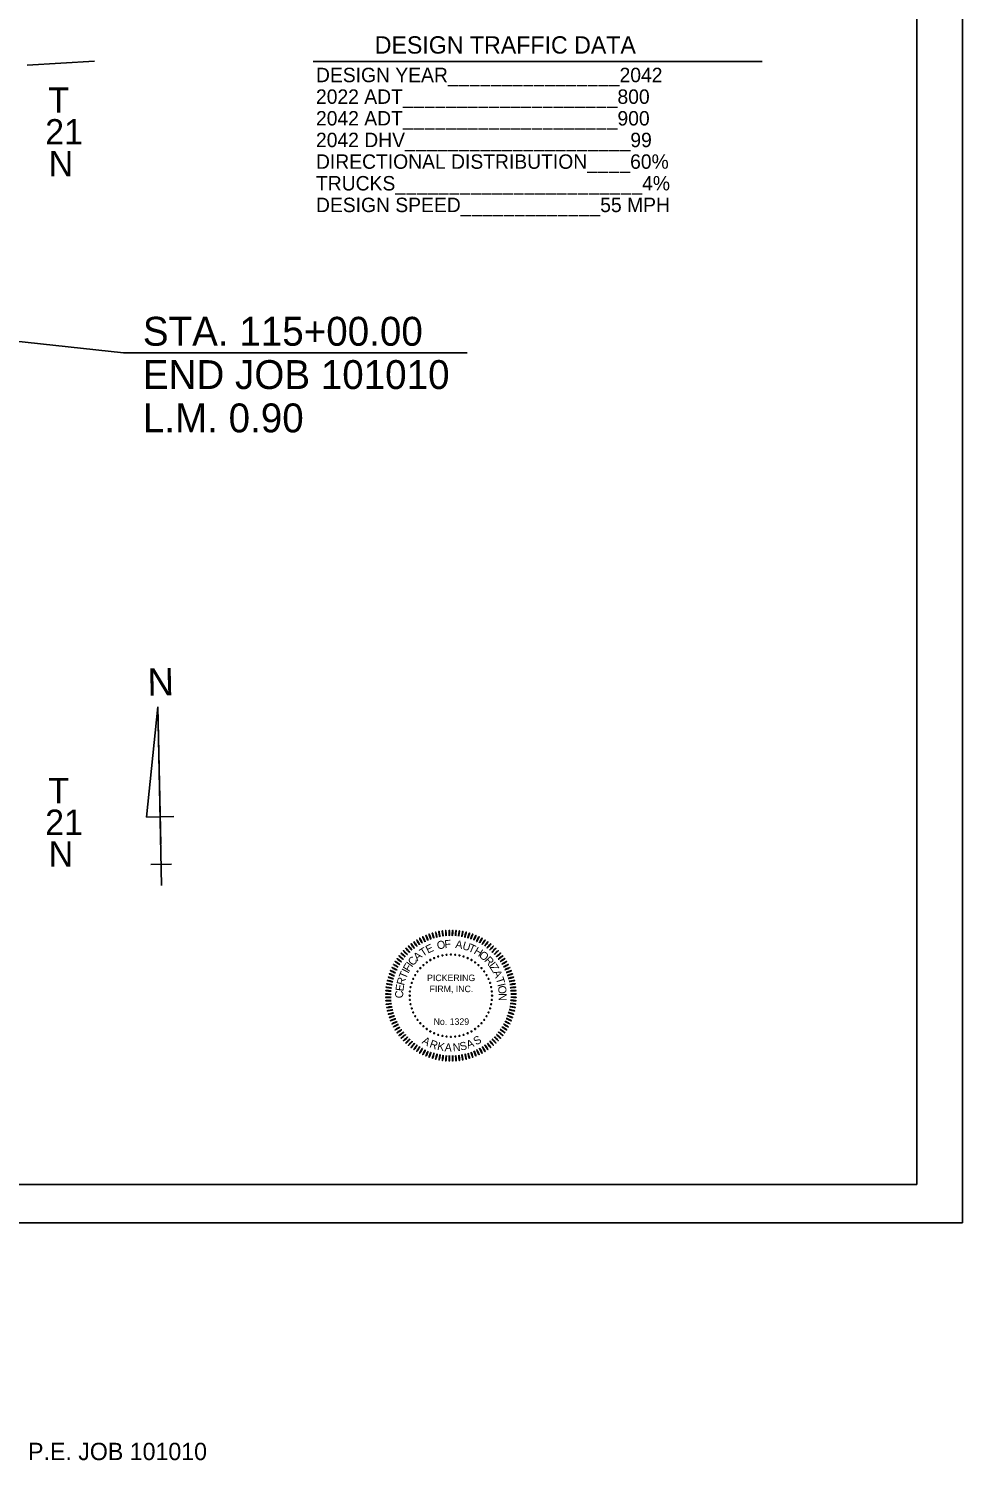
# Model space of a CAD drawing. Extents: x 1369885 to 1370219, y 379980 to 380218.
# Drawn here: x 1370121.7 to 1370218.7, y 379979.9 to 380128.7 of the extents above; entities that cross this region are included whole.
import ezdxf

# ---------------------------------------------------------------- set-up
doc = ezdxf.new("R2010")
doc.units = 0
for name, color, linetype in [('Default', 7, 'Continuous'), ('G-COA-ANNO', 7, 'Continuous'), ('G-COA-LINE', 7, 'Continuous'), ('Level 1', 7, 'Continuous'), ('Level 30', 7, 'Continuous'), ('Page Text', 7, 'Continuous'), ('R_Draft', 7, 'Continuous'), ('R_No Plot', 7, 'Continuous'), ('STAMP_PE_FOSTER-SIGNATURE', 7, 'Continuous'), ('V-ANNO', 7, 'Continuous')]:
    doc.layers.add(name, color=color, linetype=linetype)

# ---------------------------------------------------------------- blocks, each defined once
blk = doc.blocks.new('Pickering-COA AR-ENG')
at = {"layer": 'G-COA-LINE'}
for centre in [(-1.311, 4.686), (-1.311, 4.686), (-1.155, 4.812), (-1.155, 4.812), (-0.987, 4.922), (-0.987, 4.922), (-0.808, 5.013), (-0.808, 5.013), (-0.62, 5.085), (-0.62, 5.085), (-0.427, 5.137), (-0.427, 5.137), (-0.228, 5.168), (-0.228, 5.168), (-0.028, 5.179), (-0.028, 5.179), (0.173, 5.168), (0.173, 5.168), (0.371, 5.137), (0.371, 5.137), (0.565, 5.085), (0.565, 5.085), (0.752, 5.013), (0.752, 5.013), (0.931, 4.922), (0.931, 4.922), (1.099, 4.812), (1.099, 4.812), (1.255, 4.686), (1.255, 4.686), (-1.78, 4.041), (-1.78, 4.041), (-1.689, 4.22), (-1.689, 4.22), (-1.579, 4.388), (-1.579, 4.388), (-1.453, 4.544), (-1.453, 4.544), (1.397, 4.544), (1.397, 4.544), (1.524, 4.388), (1.524, 4.388), (1.633, 4.22), (1.633, 4.22), (1.724, 4.041), (1.724, 4.041), (-1.935, 3.461), (-1.935, 3.461), (-1.904, 3.66), (-1.904, 3.66), (-1.852, 3.854), (-1.852, 3.854), (1.796, 3.854), (1.796, 3.854), (1.848, 3.66), (1.848, 3.66), (1.879, 3.461), (1.879, 3.461), (-1.946, 3.261), (-1.946, 3.261), (-1.935, 3.061), (-1.935, 3.061), (-1.904, 2.862), (-1.904, 2.862), (-1.852, 2.668), (-1.852, 2.668), (1.796, 2.668), (1.796, 2.668), (1.848, 2.862), (1.848, 2.862), (1.879, 3.061), (1.879, 3.061), (1.89, 3.261), (1.89, 3.261), (-1.78, 2.481), (-1.78, 2.481), (-1.689, 2.302), (-1.689, 2.302), (-1.579, 2.134), (-1.579, 2.134), (-1.453, 1.978), (-1.453, 1.978), (1.397, 1.978), (1.397, 1.978), (1.524, 2.134), (1.524, 2.134), (1.633, 2.302), (1.633, 2.302), (1.724, 2.481), (1.724, 2.481), (-1.311, 1.836), (-1.311, 1.836), (-1.155, 1.709), (-1.155, 1.709), (-0.987, 1.6), (-0.987, 1.6), (-0.808, 1.509), (-0.808, 1.509), (-0.62, 1.437), (-0.62, 1.437), (-0.427, 1.385), (-0.427, 1.385), (-0.228, 1.354), (-0.228, 1.354), (-0.028, 1.343), (-0.028, 1.343), (0.173, 1.354), (0.173, 1.354), (0.371, 1.385), (0.371, 1.385), (0.565, 1.437), (0.565, 1.437), (0.752, 1.509), (0.752, 1.509), (0.931, 1.6), (0.931, 1.6), (1.099, 1.709), (1.099, 1.709), (1.255, 1.836), (1.255, 1.836)]:
    blk.add_circle(centre, 0.0229, dxfattribs=at)
for centre, major_axis in [((-1.287, 5.894), (0.053, -0.119)), ((-1.287, 5.894), (0.053, -0.119)), ((-1.147, 5.956), (0.047, -0.121)), ((-1.147, 5.956), (0.047, -0.121)), ((-1.005, 6.011), (0.04, -0.124)), ((-1.005, 6.011), (0.04, -0.124)), ((-0.86, 6.058), (0.034, -0.126)), ((-0.86, 6.058), (0.034, -0.126)), ((-0.712, 6.098), (0.027, -0.127)), ((-0.712, 6.098), (0.027, -0.127)), ((-0.563, 6.13), (0.02, -0.128)), ((-0.563, 6.13), (0.02, -0.128)), ((-0.412, 6.154), (0.014, -0.129)), ((-0.412, 6.154), (0.014, -0.129)), ((-0.26, 6.17), (0.006, -0.13)), ((-0.26, 6.17), (0.006, -0.13)), ((-0.107, 6.178), (0, -0.13)), ((-0.107, 6.178), (0, -0.13)), ((0.045, 6.178), (-0.007, -0.13)), ((0.045, 6.178), (-0.007, -0.13)), ((0.198, 6.171), (-0.014, -0.129)), ((0.198, 6.171), (-0.014, -0.129)), ((0.35, 6.155), (-0.02, -0.128)), ((0.35, 6.155), (-0.02, -0.128)), ((0.501, 6.131), (-0.027, -0.127)), ((0.501, 6.131), (-0.027, -0.127)), ((0.65, 6.099), (-0.034, -0.126)), ((0.65, 6.099), (-0.034, -0.126)), ((0.798, 6.06), (-0.04, -0.124)), ((0.798, 6.06), (-0.04, -0.124)), ((0.943, 6.013), (-0.047, -0.121)), ((0.943, 6.013), (-0.047, -0.121)), ((1.086, 5.958), (-0.053, -0.119)), ((1.086, 5.958), (-0.053, -0.119)), ((1.225, 5.896), (-0.059, -0.116)), ((1.225, 5.896), (-0.059, -0.116)), ((-2.147, 5.268), (0.092, -0.092)), ((-2.147, 5.268), (0.092, -0.092)), ((-2.039, 5.376), (0.087, -0.0967)), ((-2.039, 5.376), (0.087, -0.0967)), ((-1.925, 5.478), (0.082, -0.101)), ((-1.925, 5.478), (0.082, -0.101)), ((-1.807, 5.574), (0.076, -0.105)), ((-1.807, 5.574), (0.076, -0.105)), ((-1.683, 5.664), (0.071, -0.109)), ((-1.683, 5.664), (0.071, -0.109)), ((-1.555, 5.748), (0.065, -0.113)), ((-1.555, 5.748), (0.065, -0.113)), ((-1.423, 5.824), (0.059, -0.116)), ((-1.423, 5.824), (0.059, -0.116)), ((1.362, 5.827), (-0.065, -0.113)), ((1.362, 5.827), (-0.065, -0.113)), ((1.494, 5.751), (-0.071, -0.109)), ((1.494, 5.751), (-0.071, -0.109)), ((1.622, 5.668), (-0.076, -0.105)), ((1.622, 5.668), (-0.076, -0.105)), ((1.746, 5.578), (-0.082, -0.101)), ((1.746, 5.578), (-0.082, -0.101)), ((1.865, 5.482), (-0.087, -0.0967)), ((1.865, 5.482), (-0.087, -0.0967)), ((1.978, 5.38), (-0.092, -0.092)), ((1.978, 5.38), (-0.092, -0.092)), ((2.087, 5.272), (-0.0967, -0.087)), ((2.087, 5.272), (-0.0967, -0.087)), ((-2.594, 4.651), (0.113, -0.065)), ((-2.594, 4.651), (0.113, -0.065)), ((-2.517, 4.783), (0.109, -0.071)), ((-2.517, 4.783), (0.109, -0.071)), ((-2.434, 4.911), (0.105, -0.076)), ((-2.434, 4.911), (0.105, -0.076)), ((-2.345, 5.035), (0.101, -0.082)), ((-2.345, 5.035), (0.101, -0.082)), ((-2.249, 5.154), (0.0967, -0.087)), ((-2.249, 5.154), (0.0967, -0.087)), ((2.189, 5.159), (-0.101, -0.082)), ((2.189, 5.159), (-0.101, -0.082)), ((2.285, 5.04), (-0.105, -0.076)), ((2.285, 5.04), (-0.105, -0.076)), ((2.375, 4.917), (-0.109, -0.071)), ((2.375, 4.917), (-0.109, -0.071)), ((2.458, 4.789), (-0.113, -0.065)), ((2.458, 4.789), (-0.113, -0.065)), ((2.535, 4.657), (-0.116, -0.059)), ((2.535, 4.657), (-0.116, -0.059)), ((-2.827, 4.087), (0.124, -0.04)), ((-2.827, 4.087), (0.124, -0.04)), ((-2.779, 4.232), (0.121, -0.047)), ((-2.779, 4.232), (0.121, -0.047)), ((-2.725, 4.375), (0.119, -0.053)), ((-2.725, 4.375), (0.119, -0.053)), ((-2.663, 4.515), (0.116, -0.059)), ((-2.663, 4.515), (0.116, -0.059)), ((2.604, 4.521), (-0.119, -0.053)), ((2.604, 4.521), (-0.119, -0.053)), ((2.667, 4.381), (-0.121, -0.047)), ((2.667, 4.381), (-0.121, -0.047)), ((2.722, 4.238), (-0.124, -0.04)), ((2.722, 4.238), (-0.124, -0.04)), ((2.769, 4.093), (-0.126, -0.034)), ((2.769, 4.093), (-0.126, -0.034)), ((-2.945, 3.334), (0.13, -0.007)), ((-2.945, 3.334), (0.13, -0.007)), ((-2.937, 3.487), (0.129, -0.014)), ((-2.937, 3.487), (0.129, -0.014)), ((-2.921, 3.639), (0.128, -0.02)), ((-2.921, 3.639), (0.128, -0.02)), ((-2.897, 3.79), (0.127, -0.027)), ((-2.897, 3.79), (0.127, -0.027)), ((-2.866, 3.939), (0.126, -0.034)), ((-2.866, 3.939), (0.126, -0.034)), ((2.809, 3.946), (-0.127, -0.027)), ((2.809, 3.946), (-0.127, -0.027)), ((2.841, 3.796), (-0.128, -0.02)), ((2.841, 3.796), (-0.128, -0.02)), ((2.865, 3.646), (-0.129, -0.013)), ((2.865, 3.646), (-0.129, -0.013)), ((2.881, 3.494), (-0.13, -0.007)), ((2.881, 3.494), (-0.13, -0.007)), ((2.889, 3.341), (-0.13, 0)), ((2.889, 3.341), (-0.13, 0)), ((-2.945, 3.182), (0.13, 0)), ((-2.945, 3.182), (0.13, 0)), ((-2.936, 3.029), (0.13, 0.007)), ((-2.936, 3.029), (0.13, 0.007)), ((-2.92, 2.876), (0.129, 0.013)), ((-2.92, 2.876), (0.129, 0.013)), ((-2.896, 2.726), (0.128, 0.02)), ((-2.896, 2.726), (0.128, 0.02)), ((2.842, 2.733), (-0.127, 0.027)), ((2.842, 2.733), (-0.127, 0.027)), ((2.866, 2.884), (-0.128, 0.02)), ((2.866, 2.884), (-0.128, 0.02)), ((2.881, 3.036), (-0.129, 0.014)), ((2.881, 3.036), (-0.129, 0.014)), ((2.889, 3.188), (-0.13, 0.006)), ((2.889, 3.188), (-0.13, 0.006)), ((-2.864, 2.577), (0.127, 0.027)), ((-2.864, 2.577), (0.127, 0.027)), ((-2.825, 2.429), (0.126, 0.034)), ((-2.825, 2.429), (0.126, 0.034)), ((-2.777, 2.284), (0.124, 0.04)), ((-2.777, 2.284), (0.124, 0.04)), ((-2.722, 2.142), (0.121, 0.047)), ((-2.722, 2.142), (0.121, 0.047)), ((-2.66, 2.002), (0.119, 0.053)), ((-2.66, 2.002), (0.119, 0.053)), ((2.607, 2.008), (-0.116, 0.059)), ((2.607, 2.008), (-0.116, 0.059)), ((2.669, 2.148), (-0.119, 0.053)), ((2.669, 2.148), (-0.119, 0.053)), ((2.724, 2.29), (-0.121, 0.047)), ((2.724, 2.29), (-0.121, 0.047)), ((2.771, 2.436), (-0.124, 0.04)), ((2.771, 2.436), (-0.124, 0.04)), ((2.81, 2.583), (-0.126, 0.034)), ((2.81, 2.583), (-0.126, 0.034)), ((-2.591, 1.866), (0.116, 0.059)), ((-2.591, 1.866), (0.116, 0.059)), ((-2.514, 1.734), (0.113, 0.065)), ((-2.514, 1.734), (0.113, 0.065)), ((-2.431, 1.606), (0.109, 0.071)), ((-2.431, 1.606), (0.109, 0.071)), ((-2.341, 1.482), (0.105, 0.076)), ((-2.341, 1.482), (0.105, 0.076)), ((-2.244, 1.364), (0.101, 0.082)), ((-2.244, 1.364), (0.101, 0.082)), ((-2.142, 1.25), (0.0967, 0.087)), ((-2.142, 1.25), (0.0967, 0.087)), ((2.091, 1.255), (-0.092, 0.092)), ((2.091, 1.255), (-0.092, 0.092)), ((2.193, 1.369), (-0.0967, 0.087)), ((2.193, 1.369), (-0.0967, 0.087)), ((2.289, 1.488), (-0.101, 0.082)), ((2.289, 1.488), (-0.101, 0.082)), ((2.379, 1.611), (-0.105, 0.076)), ((2.379, 1.611), (-0.105, 0.076)), ((2.462, 1.739), (-0.109, 0.071)), ((2.462, 1.739), (-0.109, 0.071)), ((2.538, 1.872), (-0.113, 0.065)), ((2.538, 1.872), (-0.113, 0.065)), ((-2.034, 1.142), (0.092, 0.092)), ((-2.034, 1.142), (0.092, 0.092)), ((-1.92, 1.04), (0.087, 0.0967)), ((-1.92, 1.04), (0.087, 0.0967)), ((-1.802, 0.944), (0.082, 0.101)), ((-1.802, 0.944), (0.082, 0.101)), ((-1.678, 0.855), (0.076, 0.105)), ((-1.678, 0.855), (0.076, 0.105)), ((-1.55, 0.772), (0.071, 0.109)), ((-1.55, 0.772), (0.071, 0.109)), ((-1.417, 0.695), (0.065, 0.113)), ((-1.417, 0.695), (0.065, 0.113)), ((-1.281, 0.626), (0.059, 0.116)), ((-1.281, 0.626), (0.059, 0.116)), ((-1.141, 0.564), (0.053, 0.119)), ((-1.141, 0.564), (0.053, 0.119)), ((1.092, 0.567), (-0.047, 0.121)), ((1.092, 0.567), (-0.047, 0.121)), ((1.231, 0.629), (-0.053, 0.119)), ((1.231, 0.629), (-0.053, 0.119)), ((1.367, 0.699), (-0.059, 0.116)), ((1.367, 0.699), (-0.059, 0.116)), ((1.5, 0.775), (-0.065, 0.113)), ((1.5, 0.775), (-0.065, 0.113)), ((1.628, 0.858), (-0.071, 0.109)), ((1.628, 0.858), (-0.071, 0.109)), ((1.751, 0.948), (-0.076, 0.105)), ((1.751, 0.948), (-0.076, 0.105)), ((1.87, 1.045), (-0.082, 0.101)), ((1.87, 1.045), (-0.082, 0.101)), ((1.983, 1.147), (-0.087, 0.0967)), ((1.983, 1.147), (-0.087, 0.0967)), ((-0.999, 0.51), (0.047, 0.121)), ((-0.999, 0.51), (0.047, 0.121)), ((-0.853, 0.463), (0.04, 0.124)), ((-0.853, 0.463), (0.04, 0.124)), ((-0.706, 0.423), (0.034, 0.126)), ((-0.706, 0.423), (0.034, 0.126)), ((-0.556, 0.392), (0.027, 0.127)), ((-0.556, 0.392), (0.027, 0.127)), ((-0.405, 0.368), (0.02, 0.128)), ((-0.405, 0.368), (0.02, 0.128)), ((-0.253, 0.352), (0.014, 0.129)), ((-0.253, 0.352), (0.014, 0.129)), ((-0.101, 0.344), (0.007, 0.13)), ((-0.101, 0.344), (0.007, 0.13)), ((0.052, 0.344), (0, 0.13)), ((0.052, 0.344), (0, 0.13)), ((0.204, 0.353), (-0.007, 0.13)), ((0.204, 0.353), (-0.007, 0.13)), ((0.356, 0.369), (-0.014, 0.129)), ((0.356, 0.369), (-0.014, 0.129)), ((0.507, 0.393), (-0.02, 0.128)), ((0.507, 0.393), (-0.02, 0.128)), ((0.657, 0.425), (-0.027, 0.127)), ((0.657, 0.425), (-0.027, 0.127)), ((0.804, 0.464), (-0.034, 0.126)), ((0.804, 0.464), (-0.034, 0.126)), ((0.949, 0.512), (-0.04, 0.124)), ((0.949, 0.512), (-0.04, 0.124))]:
    blk.add_ellipse(centre, major_axis=major_axis, ratio=0.070301, dxfattribs=at)
at = {"layer": 'G-COA-ANNO'}
for s, rotation, p in [('T', 32.93533, (-1.337, 5.064)), ('E', 25.85526, (-1.098, 5.215)), ('O', 12.26193, (-0.64, 5.405)), ('F', 4.82986, (-0.315, 5.469)), ('A', 351.58912, (0.16, 5.482)), ('U', 343.80686, (0.48, 5.43)), ('T', 336.57269, (0.748, 5.349)), ('H', 329.34636, (1.006, 5.235)), ('F', 58.24564, (-1.973, 4.346)), ('I', 53.97204, (-1.839, 4.554)), ('C', 48.89667, (-1.791, 4.624)), ('A', 40.7411, (-1.586, 4.856)), ('O', 321.49368, (1.246, 5.091)), ('R', 313.2703, (1.502, 4.882)), ('I', 308.20537, (1.708, 4.653)), ('Z', 303.48765, (1.763, 4.587)), ('R', 74.84183, (-2.21, 3.716)), ('T', 67.24479, (-2.125, 4.013)), ('I', 62.51924, (-2.011, 4.27)), ('A', 295.68972, (1.917, 4.351)), ('T', 287.88395, (2.053, 4.057)), ('C', 89.69115, (-2.253, 3.141)), ('E', 82.26127, (-2.247, 3.45)), ('I', 283.1584, (2.134, 3.787)), ('O', 277.8065, (2.157, 3.704)), ('N', 269.94077, (2.197, 3.376)), ('S', 29.45104, (1.146, 0.941)), ('A', 331.00764, (-1.409, 1.057)), ('R', 339.66646, (-1.054, 0.871)), ('K', 347.96731, (-0.69, 0.746)), ('A', 356.44711, (-0.328, 0.677)), ('N', 4.79933, (0.073, 0.663)), ('S', 12.69287, (0.427, 0.701)), ('A', 21.07196, (0.776, 0.787))]:
    blk.add_text(s, height=0.373, rotation=rotation, dxfattribs=at).set_placement(p)
for s, p in [('PICKERING', (-1.138, 3.939)), ('FIRM, INC.', (-1.024, 3.425)), ('No. 1329', (-0.834, 1.9))]:
    blk.add_text(s, height=0.3049, dxfattribs=at).set_placement(p)

msp = doc.modelspace()

# ---------------------------------------------------------------- linework, layer by layer
at = {"layer": 'Level 1'}
for p, q in [((1370135.1, 380058.18), (1370133.92, 380046.74)), ((1370135.49, 380039.64), (1370135.1, 380058.18)), ((1370135.1, 380058.18), (1370135.41, 380043.92)), ((1370133.92, 380046.74), (1370136.76, 380046.79)), ((1370134.36, 380041.79), (1370136.51, 380041.85))]:
    msp.add_line(p, q, dxfattribs=at)
at = {"layer": 'Level 30'}
msp.add_lwpolyline([(1370121.53, 380124.86), (1370128.52, 380125.27)], dxfattribs=at)
at = {"layer": 'Page Text'}
msp.add_line((1370131.54, 380094.96), (1370167.25, 380094.96), dxfattribs=at)
msp.add_lwpolyline([(1370047.12, 380104.1), (1370131.54, 380094.96)], dxfattribs=at)
at = {"layer": 'R_Draft'}
msp.add_line((1370151.26, 380125.25), (1370197.92, 380125.25), dxfattribs=at)
at = {"layer": 'R_No Plot'}
msp.add_line((1369885.41, 380004.59), (1370218.74, 380004.59), dxfattribs=at)
msp.add_lwpolyline([(1369885.4, 380217.92), (1370218.74, 380217.92), (1370218.74, 380004.58), (1369885.4, 380004.58)], close=True, dxfattribs=at)
at = {"layer": 'STAMP_PE_FOSTER-SIGNATURE'}
for q in [(1370213.99, 380214.03), (1369897.81, 380008.57)]:
    msp.add_line((1370213.99, 380008.57), q, dxfattribs=at)

# ---------------------------------------------------------------- block references
at = {"layer": 'V-ANNO', "xscale": 2.231405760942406, "yscale": 2.231405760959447}
msp.add_blockref('Pickering-COA AR-ENG', (1370165.63, 380020.9), dxfattribs=at)

# ---------------------------------------------------------------- texts
at = {"layer": 'Default'}
for s, height, p in [('T', 2.63, (1370123.71, 380119.91)), ('21', 2.63, (1370123.39, 380116.62)), ('N', 2.63, (1370123.75, 380113.32)), ('T', 2.63, (1370123.71, 380048.17)), ('21', 2.63, (1370123.39, 380044.88)), ('N', 2.63, (1370123.75, 380041.59)), ('P.E. JOB 101010', 1.8, (1370121.61, 379979.92))]:
    msp.add_text(s, height=height, dxfattribs=at).set_placement(p)
at = {"layer": 'Level 1'}
msp.add_text('N', height=2.85, rotation=1.176, dxfattribs=at).set_placement((1370134.05, 380059.33))
at = {"layer": 'R_Draft'}
for s, height, p in [('DESIGN TRAFFIC DATA', 1.8, (1370157.65, 380126.06)), ('DESIGN YEAR________________2042', 1.5, (1370151.54, 380123.09)), ('2022 ADT____________________800', 1.5, (1370151.54, 380120.84)), ('2042 ADT____________________900', 1.5, (1370151.54, 380118.59)), ('2042 DHV_____________________99', 1.5, (1370151.54, 380116.34)), ('DIRECTIONAL DISTRIBUTION____60%', 1.5, (1370151.54, 380114.09)), ('TRUCKS_______________________4%', 1.5, (1370151.54, 380111.84)), ('DESIGN SPEED_____________55 MPH', 1.5, (1370151.54, 380109.59)), ('STA. 115+00.00', 3, (1370133.54, 380095.71)), ('END JOB 101010', 3, (1370133.54, 380091.21)), ('L.M. 0.90', 3, (1370133.54, 380086.71))]:
    msp.add_text(s, height=height, dxfattribs=at).set_placement(p)

doc.saveas('drawing.dxf')
